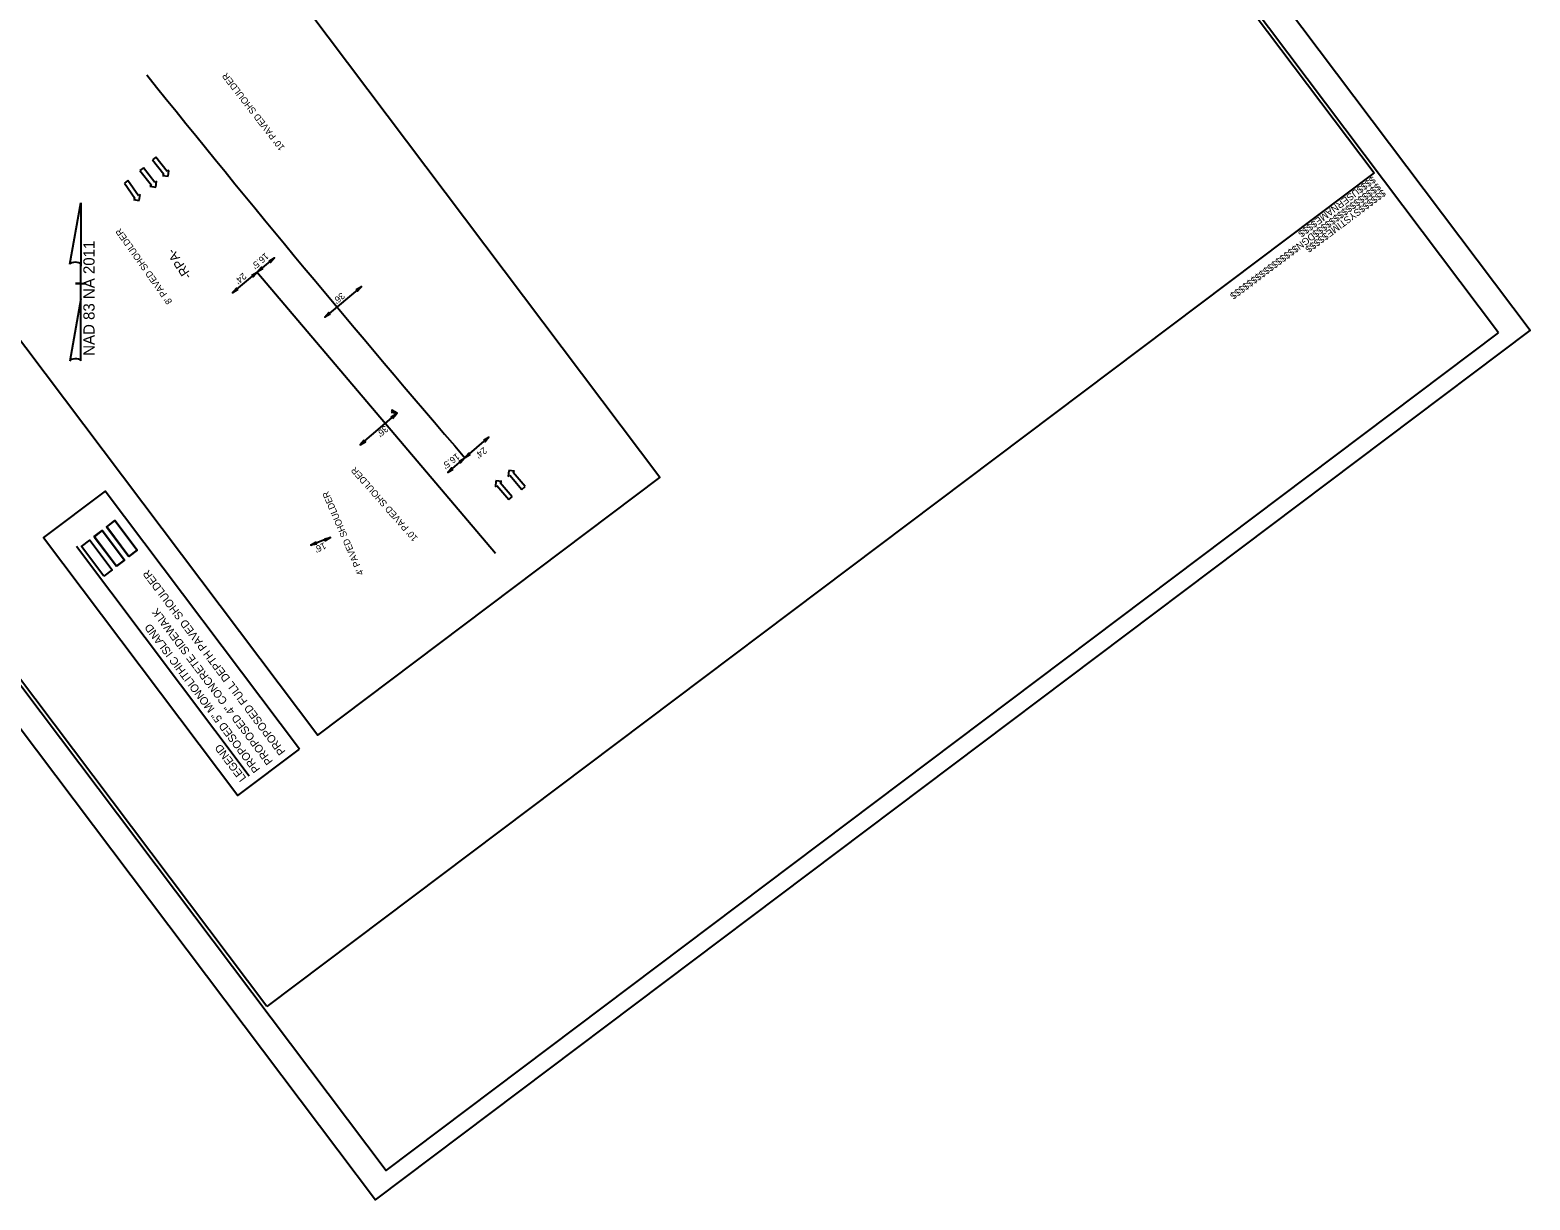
# Model space of a CAD drawing. Extents: x 1263113 to 1265001, y 775064 to 777068.
# Drawn here: x 1263865 to 1265001, y 775064 to 775951 of the extents above; entities that cross this region are included whole.
import ezdxf

# ---------------------------------------------------------------- set-up
doc = ezdxf.new("R2010")
doc.units = 0
for name, color, linetype in [('Default', 7, 'Continuous'), ('Old_Level_1', 7, 'Continuous'), ('Prop Dimension', 7, 'Continuous'), ('Prop Dimension Text', 7, 'Continuous'), ('Prop EOT', 7, 'Continuous'), ('Prop Horizontal Alignment Direction Label', 7, 'Continuous'), ('Prop Lane Arrow CELL', 7, 'Continuous'), ('Prop Lane Lines', 7, 'Continuous'), ('Prop Shade Heavy', 7, 'Continuous'), ('Prop Shade Light', 7, 'Continuous'), ('Prop Shade Medium', 7, 'Continuous'), ('Prop Terminator CELL', 7, 'Continuous'), ('Sheet Block System Information CELL', 7, 'Continuous'), ('Sheet Plot Border Inside CELL', 7, 'Continuous'), ('Sheet Plot Border Outside CELL', 7, 'Continuous'), ('Sheet Typical CELL', 7, 'Continuous')]:
    doc.layers.add(name, color=color, linetype=linetype)

msp = doc.modelspace()

# ---------------------------------------------------------------- linework, layer by layer
at = {"layer": 'Default'}
for p, q in [((1264018, 775751.8), (1264049.7, 775778.1)), ((1264115.7, 775756.5), (1264088.1, 775733.4)), ((1264114.7, 775636.5), (1264142.1, 775659.9)), ((1264092.2, 775566.2), (1264077.3, 775560.4))]:
    msp.add_line(p, q, dxfattribs=at)
at = {"layer": 'Old_Level_1'}
for p, q in [((1263894.8, 775773.4), (1263903, 775819.8)), ((1263903, 775819.8), (1263903, 775819.8)), ((1263903, 775819.8), (1263903, 775819.8)), ((1263903, 775819.8), (1263903, 775772)), ((1263903, 775747.2), (1263903, 775773.4)), ((1263903, 775772), (1263903, 775773.3)), ((1263902.6, 775758.8), (1263899, 775758.8)), ((1263899, 775758.8), (1263899, 775758.8)), ((1263899.1, 775758.8), (1263907.1, 775758.8)), ((1263903, 775747.2), (1263894.7, 775699.9)), ((1263903.1, 775700.1), (1263903, 775747.2))]:
    msp.add_line(p, q, dxfattribs=at)
for centre, start_param, end_param in [((1263898.9, 775772.9), 0.216388, 2.908219), ((1263898.9, 775699.8), 0.201328, 3.141593)]:
    msp.add_ellipse(centre, major_axis=(4.23, -0.03), ratio=0.461098, start_param=start_param, end_param=end_param, dxfattribs=at)
at = {"layer": 'Prop Dimension'}
for p, q in [((1264194, 775626.8), (1264212.2, 775642.4)), ((1264181, 775615.6), (1264193.5, 775626.3)), ((1264030.7, 775385.6), (1263899.7, 775559.5))]:
    msp.add_line(p, q, dxfattribs=at)
at = {"layer": 'Prop EOT'}
for points in [[(1263930, 775544.6), (1263913.2, 775567), (1263919.3, 775571.6), (1263936.2, 775549.2)], [(1263939.5, 775552), (1263922.7, 775574.4), (1263928.8, 775579.1), (1263945.7, 775556.7)], [(1263920.5, 775537.1), (1263903.7, 775559.5), (1263909.8, 775564.2), (1263926.7, 775541.8)]]:
    msp.add_lwpolyline(points, close=True, dxfattribs=at)
at = {"layer": 'Prop Lane Arrow CELL'}
for p, q in [((1263950.5, 775846.4), (1263947.9, 775844.3)), ((1263947.9, 775844.3), (1263956.6, 775833.3)), ((1263959.2, 775835.4), (1263950.5, 775846.4)), ((1263960, 775854.6), (1263957.4, 775852.5)), ((1263960, 775854.6), (1263957.4, 775852.5)), ((1263957.4, 775852.5), (1263966, 775841.5)), ((1263957.4, 775852.5), (1263966, 775841.5)), ((1263968.6, 775843.6), (1263960, 775854.6)), ((1263968.6, 775843.6), (1263960, 775854.6)), ((1263969.8, 775844.5), (1263968.6, 775843.6)), ((1263969.8, 775844.5), (1263968.6, 775843.6)), ((1263969.3, 775840), (1263969.8, 775844.5)), ((1263969.3, 775840), (1263969.8, 775844.5)), ((1263938.8, 775836.7), (1263936.1, 775834.9)), ((1263936.1, 775834.9), (1263944.1, 775823.4)), ((1263946.8, 775825.3), (1263938.8, 775836.7)), ((1263956.6, 775833.3), (1263955.4, 775832.4)), ((1263955.4, 775832.4), (1263959.8, 775831.8)), ((1263960.4, 775836.3), (1263959.2, 775835.4)), ((1263959.8, 775831.8), (1263960.4, 775836.3)), ((1263966, 775841.5), (1263964.9, 775840.6)), ((1263966, 775841.5), (1263964.9, 775840.6)), ((1263964.9, 775840.6), (1263969.3, 775840)), ((1263964.9, 775840.6), (1263969.3, 775840)), ((1263944.1, 775823.4), (1263942.9, 775822.5)), ((1263942.9, 775822.5), (1263947.2, 775821.7)), ((1263948.1, 775826.1), (1263946.8, 775825.3)), ((1263947.2, 775821.7), (1263948.1, 775826.1)), ((1264227.3, 775617), (1264226.9, 775612.5)), ((1264231.7, 775616.6), (1264227.3, 775617)), ((1264230.5, 775615.6), (1264231.7, 775616.6)), ((1264217.5, 775609.2), (1264217.1, 775604.7)), ((1264217.1, 775604.7), (1264218.3, 775605.7)), ((1264221.9, 775608.8), (1264217.5, 775609.2)), ((1264218.3, 775605.7), (1264227.3, 775595)), ((1264220.8, 775607.8), (1264221.9, 775608.8)), ((1264229.8, 775597.1), (1264220.8, 775607.8)), ((1264226.9, 775612.5), (1264228, 775613.5)), ((1264228, 775613.5), (1264237.1, 775602.8)), ((1264239.6, 775604.9), (1264230.5, 775615.6)), ((1264237.1, 775602.8), (1264239.6, 775604.9)), ((1264227.3, 775595), (1264229.8, 775597.1))]:
    msp.add_line(p, q, dxfattribs=at)
at = {"layer": 'Prop Lane Lines'}
msp.add_line((1264217.2, 775554.2), (1264036.5, 775767.3), dxfattribs=at)
msp.add_arc((1272837.1, 783051), 11394, 218.76592, 220.66186, dxfattribs=at)
at = {"layer": 'Prop Shade Heavy'}
for p, q in [((1263920.5, 775537.1), (1263903.7, 775559.5)), ((1263909.8, 775564.2), (1263926.7, 775541.8)), ((1263926.7, 775541.8), (1263920.5, 775537.1)), ((1263920.5, 775537.1), (1263920.5, 775537.1))]:
    msp.add_line(p, q, dxfattribs=at)
msp.add_ellipse((1263909.8, 775564.2), major_axis=(-0.000000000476, -0.000000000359), ratio=0.894427, start_param=3.141593, end_param=3.521844, dxfattribs=at)
at = {"layer": 'Prop Shade Light'}
for p, q in [((1263928.8, 775579.1), (1263922.6, 775574.4)), ((1263922.6, 775574.4), (1263939.5, 775552)), ((1263939.5, 775552), (1263945.7, 775556.7))]:
    msp.add_line(p, q, dxfattribs=at)
msp.add_lwpolyline([(1263945.7, 775556.7), (1263928.8, 775579.1)], dxfattribs=at)
msp.add_ellipse((1263922.6, 775574.4), major_axis=(-0.018, -0.0081), ratio=0.299083, start_param=5.584494, end_param=6.511789, dxfattribs=at)
at = {"layer": 'Prop Shade Medium'}
for p, q in [((1263919.3, 775571.6), (1263913.1, 775566.9)), ((1263913.1, 775566.9), (1263930, 775544.6)), ((1263930, 775544.6), (1263936.2, 775549.2))]:
    msp.add_line(p, q, dxfattribs=at)
msp.add_lwpolyline([(1263936.2, 775549.2), (1263919.3, 775571.6)], dxfattribs=at)
msp.add_ellipse((1263913.1, 775566.9), major_axis=(-0.018, -0.0081), ratio=0.299083, start_param=5.584494, end_param=6.511789, dxfattribs=at)
at = {"layer": 'Prop Terminator CELL'}
for points in [[(1264045.8, 775775.8), (1264049.7, 775778.1), (1264046.7, 775774.6), (1264046.7, 775775.6)], [(1264032.6, 775765), (1264036.6, 775767.3), (1264033.6, 775763.8), (1264033.6, 775764.7)], [(1264041, 775769.9), (1264037, 775767.6), (1264040, 775771.1), (1264040, 775770.1)], [(1264021.9, 775754.1), (1264017.9, 775751.8), (1264020.9, 775755.3), (1264021, 775754.4)], [(1264111.6, 775754.1), (1264115.6, 775756.4), (1264112.6, 775752.9), (1264112.6, 775753.9)], [(1264091.9, 775735.6), (1264088, 775733.3), (1264090.9, 775736.8), (1264091, 775735.9)], [(1264138.2, 775661.3), (1264142.7, 775660.4), (1264138.8, 775662.8), (1264139, 775661.9)], [(1264139.2, 775656.4), (1264142.1, 775659.9), (1264138.1, 775657.5), (1264139.1, 775657.3)], [(1264117.6, 775640), (1264114.7, 775636.5), (1264118.7, 775638.9), (1264117.7, 775639.1)], [(1264208.3, 775640.1), (1264212.2, 775642.4), (1264209.3, 775638.8), (1264209.2, 775639.8)], [(1264197.9, 775629.1), (1264194, 775626.8), (1264196.9, 775630.3), (1264197, 775629.3)], [(1264184.9, 775617.9), (1264181, 775615.6), (1264183.9, 775619.1), (1264184, 775618.1)], [(1264189.6, 775624), (1264193.5, 775626.3), (1264190.6, 775622.8), (1264190.5, 775623.8)], [(1264081.8, 775561.4), (1264077.3, 775560.4), (1264081.2, 775562.8), (1264081, 775561.9)], [(1264087.8, 775565.3), (1264092.2, 775566.2), (1264088.3, 775563.9), (1264088.5, 775564.8)]]:
    msp.add_lwpolyline(points, close=True, dxfattribs=at)
at = {"layer": 'Sheet Block System Information CELL'}
msp.add_line((1264882.7, 775842.6), (1264882.7, 775842.6), dxfattribs=at)
at = {"layer": 'Sheet Plot Border Inside CELL'}
msp.add_lwpolyline([(1264977.1, 775721.5), (1263974.7, 777052.3), (1263132, 776417.6), (1264134.4, 775086.8)], close=True, dxfattribs=at)
at = {"layer": 'Sheet Plot Border Outside CELL'}
msp.add_lwpolyline([(1263113.4, 776409.1), (1264126.2, 775064.4), (1265000.9, 775723.2), (1263988, 777067.9)], close=True, dxfattribs=at)
at = {"layer": 'Sheet Typical CELL'}
for p, q in [((1263980.2, 777040.8), (1264882.7, 775842.6)), ((1264044, 775210.9), (1263141.5, 776409.1)), ((1264882.7, 775842.6), (1264044, 775210.9))]:
    msp.add_line(p, q, dxfattribs=at)
for points in [[(1263432.6, 776279.6), (1264082.6, 775416.6), (1264341.8, 775611.8), (1263691.8, 776474.8)], [(1264068.7, 775406), (1263921.4, 775601.5), (1263874.8, 775566.4), (1264022, 775370.8)]]:
    msp.add_lwpolyline(points, close=True, dxfattribs=at)

# ---------------------------------------------------------------- texts
at = {"layer": 'Old_Level_1'}
msp.add_text('NAD 83 NA 2011', height=8.5, rotation=90, dxfattribs=at).set_placement((1263913.5, 775704))
at = {"layer": 'Prop Dimension Text'}
for s, height, rotation, p in [("10' PAVED SHOULDER", 5, 127.7256, (1264057.8, 775861.8)), ("8' PAVED SHOULDER", 5, 125.2625, (1263972.6, 775745.1)), ("16.5'", 5, 221.0554, (1264042.8, 775782.4)), ("24'", 5, 221.0554, (1264025.9, 775767.2)), ("36'", 5, 221.0554, (1264100.4, 775752.3)), ("36'", 5, 221.0554, (1264133.4, 775651.5)), ("16.5'", 5, 217.7256, (1264187.7, 775630.5)), ("24'", 5, 217.7256, (1264208.3, 775635.1)), ("10' PAVED SHOULDER", 5, 131.3269, (1264158.7, 775566)), ("4' PAVED SHOULDER", 5, 113.3488, (1264117.6, 775538.9)), ("16'", 5, 205.3915, (1264087.4, 775562.8)), ('PROPOSED FULL DEPTH PAVED SHOULDER ', 6, 126.9877, (1264058.4, 775404.2)), ('PROPOSED 4" CONCRETE SIDEWALK', 6, 126.9877, (1264048.9, 775396.8)), ('PROPOSED 5" MONOLITHIC ISLAND', 6, 126.9877, (1264039.2, 775390.8)), ('LEGEND', 6, 126.9877, (1264028.7, 775384.1))]:
    msp.add_text(s, height=height, rotation=rotation, dxfattribs=at).set_placement(p)
at = {"layer": 'Prop Horizontal Alignment Direction Label'}
msp.add_text('-RPA-', height=7, rotation=123.4029, dxfattribs=at).set_placement((1263987.4, 775764.7))
at = {"layer": 'Sheet Block System Information CELL'}
for s, p in [('$$$$$$$$$$$$$$$$DGN$$$$$$$$$$$$$$$$', (1264885.4, 775835.1)), ('$$$$USERNAME$$$$', (1264881.5, 775840.4)), ('$$$$$$SYSTIME$$$$$', (1264889.1, 775830.3))]:
    msp.add_text(s, height=5.25, rotation=216.9874, dxfattribs=at).set_placement(p)

doc.saveas('drawing.dxf')
